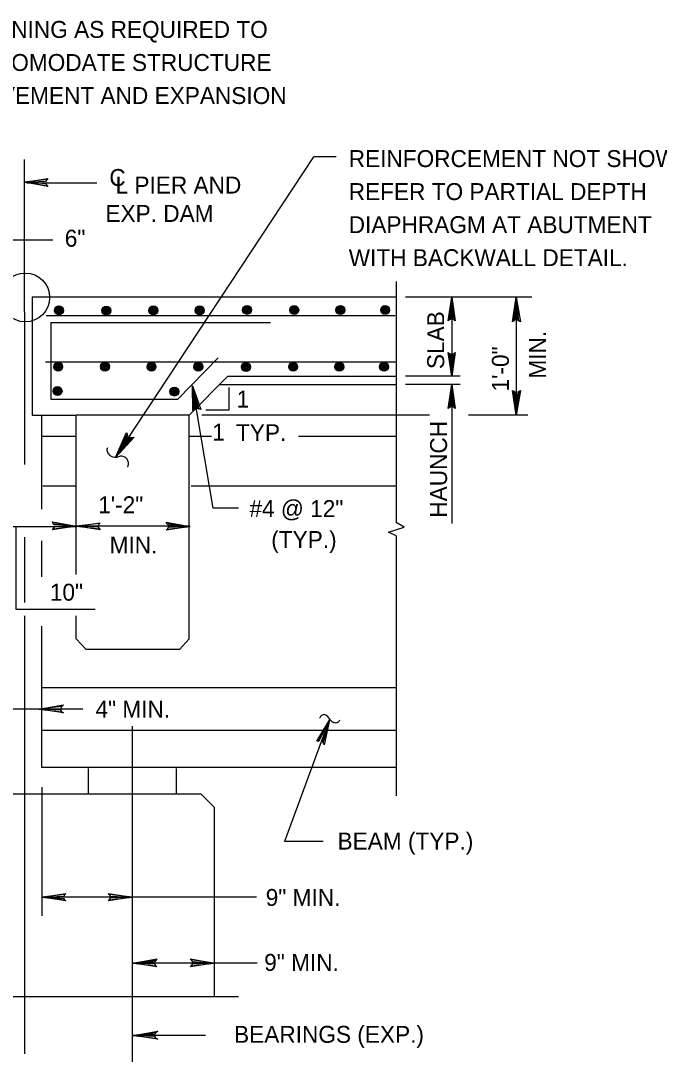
# Model space of a CAD drawing. Extents: x 638653 to 642302, y 298557 to 300414.
# Drawn here: x 640002.4 to 640115.6, y 299837.9 to 300021.7 of the extents above; entities that cross this region are included whole.
import ezdxf

# ---------------------------------------------------------------- set-up
doc = ezdxf.new("R2010")
doc.units = 0
doc.layers.add('1', color=7, linetype='Continuous')

msp = doc.modelspace()

# ---------------------------------------------------------------- linework, layer by layer
at = {"layer": '1'}
for p, q in [((640003.03, 299997.07), (640003.06, 299942.98)), ((640019.22, 299944.23), (640054.34, 299997.55)), ((640058.32, 299997.55), (640054.34, 299997.55)), ((640003.49, 299992.89), (640015.93, 299992.89)), ((640008.1, 299982.75), (639997.04, 299982.75)), ((640068.99, 299975.43), (640068.99, 299932.67)), ((640068.99, 299972.67), (640004.46, 299972.67)), ((640004.46, 299972.67), (640004.46, 299951.73)), ((640093.01, 299972.67), (640070.59, 299972.67)), ((640078.81, 299972.67), (640078.81, 299958.61)), ((640090.22, 299972.67), (640090.22, 299951.73)), ((640006.91, 299969.42), (640068.8, 299969.42)), ((640007.74, 299968.15), (640046.7, 299968.15)), ((640068.99, 299961.09), (640006.79, 299961.09)), ((640032.27, 299951.73), (640039.15, 299958.61)), ((640039.15, 299958.61), (640068.99, 299958.61)), ((640080.31, 299958.61), (640070.59, 299958.61)), ((640036.55, 299935.23), (640032.86, 299956.94)), ((640037.69, 299957.15), (640068.99, 299957.15)), ((640039.38, 299952.65), (640039.38, 299956.62)), ((640080.31, 299957.15), (640070.59, 299957.15)), ((640078.81, 299957.15), (640078.81, 299932.49)), ((640035.24, 299952.65), (640039.38, 299952.65)), ((640004.46, 299951.73), (640012.12, 299951.73)), ((640006.18, 299935.08), (640006.18, 299951.73)), ((640032.27, 299951.73), (640012.27, 299951.73)), ((640012.27, 299923.48), (640012.27, 299951.73)), ((640032.27, 299912.04), (640032.27, 299951.73)), ((640074.89, 299951.73), (640034.52, 299951.73)), ((640092.3, 299951.73), (640081.8, 299951.73)), ((640012.27, 299947.95), (640006.18, 299947.95)), ((640036.22, 299947.95), (640032.27, 299947.95)), ((640068.99, 299947.95), (640051.64, 299947.95)), ((640012.27, 299939.14), (640006.32, 299939.14)), ((640068.99, 299939.14), (640032.62, 299939.14)), ((640041.02, 299935.23), (640036.55, 299935.23)), ((639994.06, 299932), (640012.35, 299932)), ((640032.26, 299932.02), (640012.26, 299932.02)), ((640003.06, 299930.08), (640003.06, 299918.5)), ((640006.18, 299923.03), (640006.18, 299929.46)), ((640068.99, 299930.33), (640068.99, 299884.23)), ((640003.06, 299916.15), (640003.06, 299838.48)), ((640012.27, 299912.04), (640012.27, 299916.15)), ((640006.18, 299889.23), (640006.18, 299914.33)), ((640013.99, 299910.17), (640012.27, 299912.04)), ((640030.56, 299910.17), (640032.27, 299912.04)), ((640030.56, 299910.17), (640013.99, 299910.17)), ((640068.99, 299903.38), (640006.18, 299903.38)), ((640005.61, 299899.58), (639999.83, 299899.58)), ((640013.43, 299899.58), (640005.61, 299899.58)), ((640057.12, 299897.83), (640049.15, 299876.11)), ((640068.99, 299895.81), (640006.18, 299895.81)), ((640022.17, 299896.58), (640022.17, 299837.04)), ((640068.99, 299889.23), (640006.18, 299889.23)), ((640014.35, 299889.08), (640014.35, 299884.54)), ((640029.98, 299889.08), (640029.98, 299884.54)), ((640034.38, 299884.54), (639970.74, 299884.54)), ((640006.18, 299885.78), (640006.18, 299862.98)), ((640036.71, 299882.21), (640034.38, 299884.54)), ((640036.71, 299882.21), (640036.71, 299848.61)), ((640056.02, 299876.11), (640049.15, 299876.11)), ((640022.01, 299866.26), (640006.18, 299866.26)), ((640044.2, 299866.26), (640022.01, 299866.26)), ((640039.35, 299866.26), (640022.01, 299866.26)), ((640036.71, 299854.54), (640022.48, 299854.54)), ((640039.67, 299854.54), (640035.14, 299854.54)), ((640044.35, 299854.54), (640036.71, 299854.54)), ((640041.02, 299848.61), (640000.24, 299848.61)), ((640035.18, 299841.73), (640022.32, 299841.73))]:
    msp.add_line(p, q, dxfattribs=at)
for points in [[(640007.09, 299992.42), (640006.93, 299992.73), (640003.03, 299993.05), (640007.09, 299992.42), (640007.24, 299992.26), (640003.03, 299993.05), (640006.93, 299993.2), (640007.09, 299993.51), (640003.03, 299993.05), (640007.24, 299993.67), (640007.09, 299993.51)], [(640078.34, 299968.61), (640078.65, 299968.76), (640078.81, 299972.67), (640078.34, 299968.61), (640078.19, 299968.45), (640078.81, 299972.67), (640078.97, 299968.76), (640079.28, 299968.61), (640078.81, 299972.67), (640079.44, 299968.45), (640079.28, 299968.61)], [(640089.75, 299968.45), (640090.06, 299968.61), (640090.22, 299972.67), (640089.75, 299968.45), (640089.59, 299968.29), (640090.22, 299972.67), (640090.37, 299968.61), (640090.69, 299968.45), (640090.22, 299972.67), (640091, 299968.29), (640090.69, 299968.45)], [(640007.74, 299968.15), (640007.74, 299954.54), (640030.24, 299954.54), (640037.43, 299961.89)], [(640079.28, 299962.67), (640078.97, 299962.51), (640078.81, 299958.61), (640079.28, 299962.67), (640079.44, 299962.83), (640078.81, 299958.61), (640078.65, 299962.51), (640078.34, 299962.67), (640078.81, 299958.61), (640078.19, 299962.83), (640078.34, 299962.67)], [(640033.06, 299952.7), (640033.34, 299952.9), (640032.86, 299956.94), (640033.06, 299952.7), (640032.93, 299952.52), (640032.86, 299956.94), (640033.65, 299952.95), (640033.98, 299952.84), (640032.86, 299956.94), (640034.32, 299952.74), (640033.98, 299952.84)], [(640078.34, 299953.08), (640078.65, 299953.24), (640078.81, 299957.15), (640078.34, 299953.08), (640078.19, 299952.93), (640078.81, 299957.15), (640078.97, 299953.24), (640079.28, 299953.08), (640078.81, 299957.15), (640079.44, 299952.93), (640079.28, 299953.08)], [(640090.84, 299955.95), (640090.53, 299955.79), (640090.22, 299951.73), (640090.84, 299955.95), (640091, 299956.11), (640090.22, 299951.73), (640090.06, 299955.79), (640089.75, 299955.95), (640090.22, 299951.73), (640089.59, 299956.11), (640089.75, 299955.95)], [(640022.17, 299947.68), (640021.84, 299947.79), (640019.22, 299944.23), (640022.17, 299947.68), (640022.5, 299947.8), (640019.22, 299944.23), (640021.39, 299948.01), (640021.28, 299948.34), (640019.22, 299944.23), (640021.17, 299948.67), (640021.28, 299948.34)], [(640008.19, 299932.48), (640008.35, 299932.33), (640012.26, 299932.02), (640008.19, 299932.48), (640008.04, 299932.8), (640012.26, 299932.02), (640008.35, 299931.86), (640008.19, 299931.55), (640012.26, 299932.02), (640008.04, 299931.39), (640008.19, 299931.55)], [(640016.36, 299931.55), (640016.2, 299931.86), (640012.3, 299932.02), (640016.36, 299931.55), (640016.52, 299931.39), (640012.3, 299932.02), (640016.2, 299932.18), (640016.36, 299932.49), (640012.3, 299932.02), (640016.52, 299932.64), (640016.36, 299932.49)], [(640028.37, 299932.43), (640028.52, 299932.27), (640032.43, 299931.96), (640028.37, 299932.43), (640028.21, 299932.74), (640032.43, 299931.96), (640028.52, 299931.8), (640028.37, 299931.49), (640032.43, 299931.96), (640028.21, 299931.33), (640028.37, 299931.49)], [(640068.99, 299930.33), (640067.59, 299930.95), (640070.4, 299931.89), (640068.99, 299932.67)], [(640001.55, 299932), (640001.55, 299917.32), (640015.59, 299917.32)], [(640009.68, 299899.11), (640009.52, 299899.42), (640005.61, 299899.58), (640009.68, 299899.11), (640009.99, 299898.96), (640005.61, 299899.58), (640009.52, 299899.74), (640009.68, 299900.05), (640005.61, 299899.58), (640009.99, 299900.36), (640009.68, 299900.05)], [(640055.09, 299893.92), (640055.4, 299894.08), (640057.12, 299897.67), (640055.09, 299893.92), (640054.93, 299893.92), (640057.12, 299897.67), (640055.87, 299893.92), (640056.02, 299893.61), (640057.12, 299897.67), (640056.18, 299893.29), (640056.02, 299893.61)], [(640010.24, 299865.79), (640010.09, 299865.95), (640006.18, 299866.26), (640010.24, 299865.79), (640010.4, 299865.64), (640006.18, 299866.26), (640010.09, 299866.42), (640010.24, 299866.73), (640006.18, 299866.26), (640010.4, 299866.89), (640010.24, 299866.73)], [(640018.1, 299866.73), (640018.26, 299866.42), (640022.17, 299866.26), (640018.1, 299866.73), (640017.95, 299866.89), (640022.17, 299866.26), (640018.26, 299866.11), (640018.1, 299865.79), (640022.17, 299866.26), (640017.95, 299865.64), (640018.1, 299865.79)], [(640026.39, 299854.08), (640026.23, 299854.39), (640022.32, 299854.54), (640026.39, 299854.08), (640026.54, 299853.92), (640022.32, 299854.54), (640026.23, 299854.86), (640026.39, 299855.01), (640022.32, 299854.54), (640026.54, 299855.33), (640026.39, 299855.01)], [(640032.65, 299855.17), (640032.8, 299854.86), (640036.71, 299854.54), (640032.65, 299855.17), (640032.49, 299855.33), (640036.71, 299854.54), (640032.8, 299854.39), (640032.65, 299854.08), (640036.71, 299854.54), (640032.49, 299853.92), (640032.65, 299854.08)], [(640026.39, 299841.26), (640026.23, 299841.58), (640022.32, 299841.73), (640026.39, 299841.26), (640026.7, 299841.11), (640022.32, 299841.73), (640026.23, 299842.04), (640026.39, 299842.2), (640022.32, 299841.73), (640026.7, 299842.51), (640026.39, 299842.2)]]:
    msp.add_lwpolyline(points, dxfattribs=at)
for centre, radius in [((640003.21, 299972.59), 4.33), ((640009.18, 299970.29), 0.791), ((640009.18, 299970.29), 0.659), ((640009.18, 299970.29), 0.527), ((640017.58, 299970.26), 0.791), ((640017.58, 299970.26), 0.659), ((640017.58, 299970.26), 0.527), ((640025.93, 299970.29), 0.791), ((640025.93, 299970.29), 0.659), ((640025.93, 299970.29), 0.527), ((640034.12, 299970.29), 0.791), ((640034.12, 299970.29), 0.659), ((640034.12, 299970.29), 0.527), ((640042.54, 299970.39), 0.791), ((640042.54, 299970.39), 0.659), ((640042.54, 299970.39), 0.527), ((640042.54, 299970.39), 0.396), ((640050.89, 299970.36), 0.791), ((640050.89, 299970.36), 0.659), ((640050.89, 299970.36), 0.527), ((640059.08, 299970.36), 0.791), ((640059.08, 299970.36), 0.659), ((640059.08, 299970.36), 0.527), ((640067.01, 299970.36), 0.791), ((640067.01, 299970.36), 0.659), ((640067.01, 299970.36), 0.527), ((640009.18, 299970.29), 0.396), ((640009.18, 299970.29), 0.264), ((640009.18, 299970.29), 0.132), ((640017.58, 299970.26), 0.396), ((640017.58, 299970.26), 0.264), ((640017.58, 299970.26), 0.132), ((640025.93, 299970.29), 0.396), ((640025.93, 299970.29), 0.264), ((640025.93, 299970.29), 0.132), ((640034.12, 299970.29), 0.396), ((640034.12, 299970.29), 0.264), ((640034.12, 299970.29), 0.132), ((640042.54, 299970.39), 0.264), ((640042.54, 299970.39), 0.132), ((640050.89, 299970.36), 0.396), ((640050.89, 299970.36), 0.264), ((640050.89, 299970.36), 0.132), ((640059.08, 299970.36), 0.396), ((640059.08, 299970.36), 0.264), ((640059.08, 299970.36), 0.132), ((640067.01, 299970.36), 0.396), ((640067.01, 299970.36), 0.264), ((640067.01, 299970.36), 0.132), ((640009.05, 299960.31), 0.791), ((640009.05, 299960.31), 0.659), ((640009.05, 299960.31), 0.527), ((640009.05, 299960.31), 0.396), ((640009.05, 299960.31), 0.264), ((640009.05, 299960.31), 0.132), ((640017.36, 299960.33), 0.791), ((640017.36, 299960.33), 0.659), ((640017.36, 299960.33), 0.527), ((640017.36, 299960.33), 0.396), ((640017.36, 299960.33), 0.264), ((640017.36, 299960.33), 0.132), ((640025.6, 299960.31), 0.791), ((640025.6, 299960.31), 0.659), ((640025.6, 299960.31), 0.527), ((640025.6, 299960.31), 0.396), ((640025.6, 299960.31), 0.264), ((640025.6, 299960.31), 0.132), ((640033.88, 299960.31), 0.791), ((640033.88, 299960.31), 0.659), ((640033.88, 299960.31), 0.527), ((640033.88, 299960.31), 0.396), ((640033.88, 299960.31), 0.264), ((640033.88, 299960.31), 0.132), ((640042.35, 299960.27), 0.791), ((640042.35, 299960.27), 0.659), ((640042.35, 299960.27), 0.527), ((640042.35, 299960.27), 0.396), ((640042.35, 299960.27), 0.264), ((640042.35, 299960.27), 0.132), ((640050.7, 299960.3), 0.791), ((640050.7, 299960.3), 0.659), ((640050.7, 299960.3), 0.527), ((640050.7, 299960.3), 0.396), ((640050.7, 299960.3), 0.264), ((640050.7, 299960.3), 0.132), ((640058.89, 299960.3), 0.791), ((640058.89, 299960.3), 0.659), ((640058.89, 299960.3), 0.527), ((640058.89, 299960.3), 0.396), ((640058.89, 299960.3), 0.264), ((640058.89, 299960.3), 0.132), ((640066.82, 299960.3), 0.791), ((640066.82, 299960.3), 0.659), ((640066.82, 299960.3), 0.527), ((640066.82, 299960.3), 0.396), ((640066.82, 299960.3), 0.264), ((640066.82, 299960.3), 0.132), ((640008.94, 299955.99), 0.791), ((640008.94, 299955.99), 0.659), ((640008.94, 299955.99), 0.527), ((640008.94, 299955.99), 0.396), ((640008.94, 299955.99), 0.264), ((640008.94, 299955.99), 0.132), ((640029.65, 299955.91), 0.791), ((640029.65, 299955.91), 0.659), ((640029.65, 299955.91), 0.527), ((640029.65, 299955.91), 0.396), ((640029.65, 299955.91), 0.264), ((640029.65, 299955.91), 0.132)]:
    msp.add_circle(centre, radius, dxfattribs=at)
for points in [[(640021.42, 299942.49), (640021.52, 299943.04), (640021.07, 299944.14), (640020.07, 299944.46), (640019.41, 299944.24), (640018.64, 299944.34), (640017.86, 299945.1), (640017.74, 299945.43), (640017.85, 299945.99)], [(640058.99, 299897.67), (640058.52, 299897.2), (640057.9, 299897.2), (640057.43, 299897.51), (640056.96, 299898.14), (640056.34, 299898.61), (640055.71, 299898.45), (640055.4, 299897.98)]]:
    msp.add_spline(points, degree=3, dxfattribs=at)

# ---------------------------------------------------------------- texts
for s, p in [('OPENING AS REQUIRED TO', (639992.26, 300018.61)), ('ACCOMODATE STRUCTURE', (639992.26, 300012.75)), ('MOVEMENT AND EXPANSION', (639992.26, 300006.89)), ('REINFORCEMENT NOT SHOWN.', (640060.55, 299995.71)), ('C', (640018.12, 299992.36)), ('L PIER AND', (640019.22, 299991.02)), ('REFER TO PARTIAL DEPTH', (640060.55, 299989.86)), (' EXP. DAM', (640016.31, 299985.99)), ('DIAPHRAGM AT ABUTMENT', (640060.55, 299984)), ('6"', (640010.22, 299981.59)), ('WITH BACKWALL DETAIL.', (640060.55, 299978.14)), ('1', (640040.69, 299953.07)), ('1', (640036.35, 299947.2)), ('TYP.', (640040.57, 299947.12)), ('1\'-2"', (640016.15, 299934.33)), ('#4 @ 12"', (640042.95, 299933.66)), ('(TYP.)', (640046.82, 299928.17)), ('MIN.', (640018.16, 299927.2)), ('10"', (640007.57, 299918.83)), ('4" MIN.', (640015.66, 299898.09)), ('BEAM (TYP.)', (640058.57, 299874.71)), ('9" MIN.', (640045.84, 299864.71)), ('9" MIN.', (640045.57, 299853.2)), ('  BEARINGS (EXP.)', (640038, 299840.44))]:
    msp.add_text(s, height=3, dxfattribs=at).set_placement(p)
for s, p in [('SLAB', (640077.47, 299959.89)), ('MIN.', (640095.51, 299958.21)), ('1\'-0"', (640088.94, 299955.92)), ('HAUNCH', (640077.98, 299933.54))]:
    msp.add_text(s, height=3, rotation=90, dxfattribs=at).set_placement(p)

doc.saveas('drawing.dxf')
